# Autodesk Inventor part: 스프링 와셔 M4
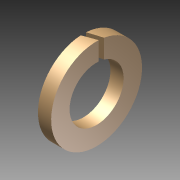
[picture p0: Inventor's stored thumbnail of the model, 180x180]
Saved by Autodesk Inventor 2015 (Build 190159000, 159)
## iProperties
Created: 2026-04
Part Number: 스프링 와셔 M4
Material: 일반
Document SubType Name: Modeling
Designer: User
Density: 1 g/cm^3
Appearance: 기본값
Author: User
Author: jhkim
Description: 스프링 잠금 와셔
Creation Date: 2026-03-26
Sending System: Autodesk Inventor 2026
Preprocessor: ST-DEVELOPER v20.1
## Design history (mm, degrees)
node "스프링 와셔 M41"
body "Solid1"
node "기준1"
